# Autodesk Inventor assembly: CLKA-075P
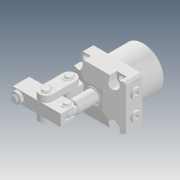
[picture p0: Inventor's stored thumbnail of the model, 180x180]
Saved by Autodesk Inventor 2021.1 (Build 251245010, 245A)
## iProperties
Created: 2018-07
Part Number: CLKA-075P
Description: STEP AP203
Document SubType Name: Assembly
Designer: user
Title: CLKA-075P.STEP
Revision Number: ÈÎºÎ
Sending System: SolidWorks 2015
Preprocessor: SwSTEP 2.0
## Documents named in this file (11)
- D:\Vault_2016\Projekty\Clamptek\Hydraulic\CLKA-P\Inventor\CLKA-075P\CLKA-075P.iam
- D:\Vault_2016\Projekty\Clamptek\Hydraulic\CLKA-P\Inventor\CLKA-075P\dangjuan75.ipt
- D:\Vault_2016\Projekty\Clamptek\Hydraulic\CLKA-P\Inventor\CLKA-075P\duanxiao75.ipt
- D:\Vault_2016\Projekty\Clamptek\Hydraulic\CLKA-P\Inventor\CLKA-075P\liangan75.ipt
- D:\Vault_2016\Projekty\Clamptek\Hydraulic\CLKA-P\Inventor\CLKA-075P\luosi75.ipt
- D:\Vault_2016\Projekty\Clamptek\Hydraulic\CLKA-P\Inventor\CLKA-075P\m12luomo.ipt
- D:\Vault_2016\Projekty\Clamptek\Hydraulic\CLKA-P\Inventor\CLKA-075P\yabi75.ipt
- D:\Vault_2016\Projekty\Clamptek\Hydraulic\CLKA-P\Inventor\CLKA-075P\zhangxiao75.ipt
- D:\Vault_2016\Projekty\Clamptek\Hydraulic\CLKA-P\Inventor\CLKA-075P\dangjuan01.ipt
- D:\Vault_2016\Projekty\Clamptek\Hydraulic\CLKA-P\Inventor\CLKA-075P\CLKA-075P-benti.ipt
- D:\Vault_2016\Projekty\Clamptek\Hydraulic\CLKA-P\Inventor\CLKA-075P\¶ÂÍ·G4-1.ipt
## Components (17 placed, 17 different names)
1. dangjuan75_1
2. duanxiao75_2
3. liangan75_3
4. luosi75_4
5. m12luomo_5
6. yabi75_6
7. zhangxiao75_7
8. liangan75_8
9. zhangxiao75_9
10. dangjuan75_10
11. dangjuan75_11
12. dangjuan75_12
13. dangjuan01_13
14. dangjuan01_14
15. CLKA-075P-benti_15
16. ¶ÂÍ·G4-1_16
17. ¶ÂÍ·G4-1_17
